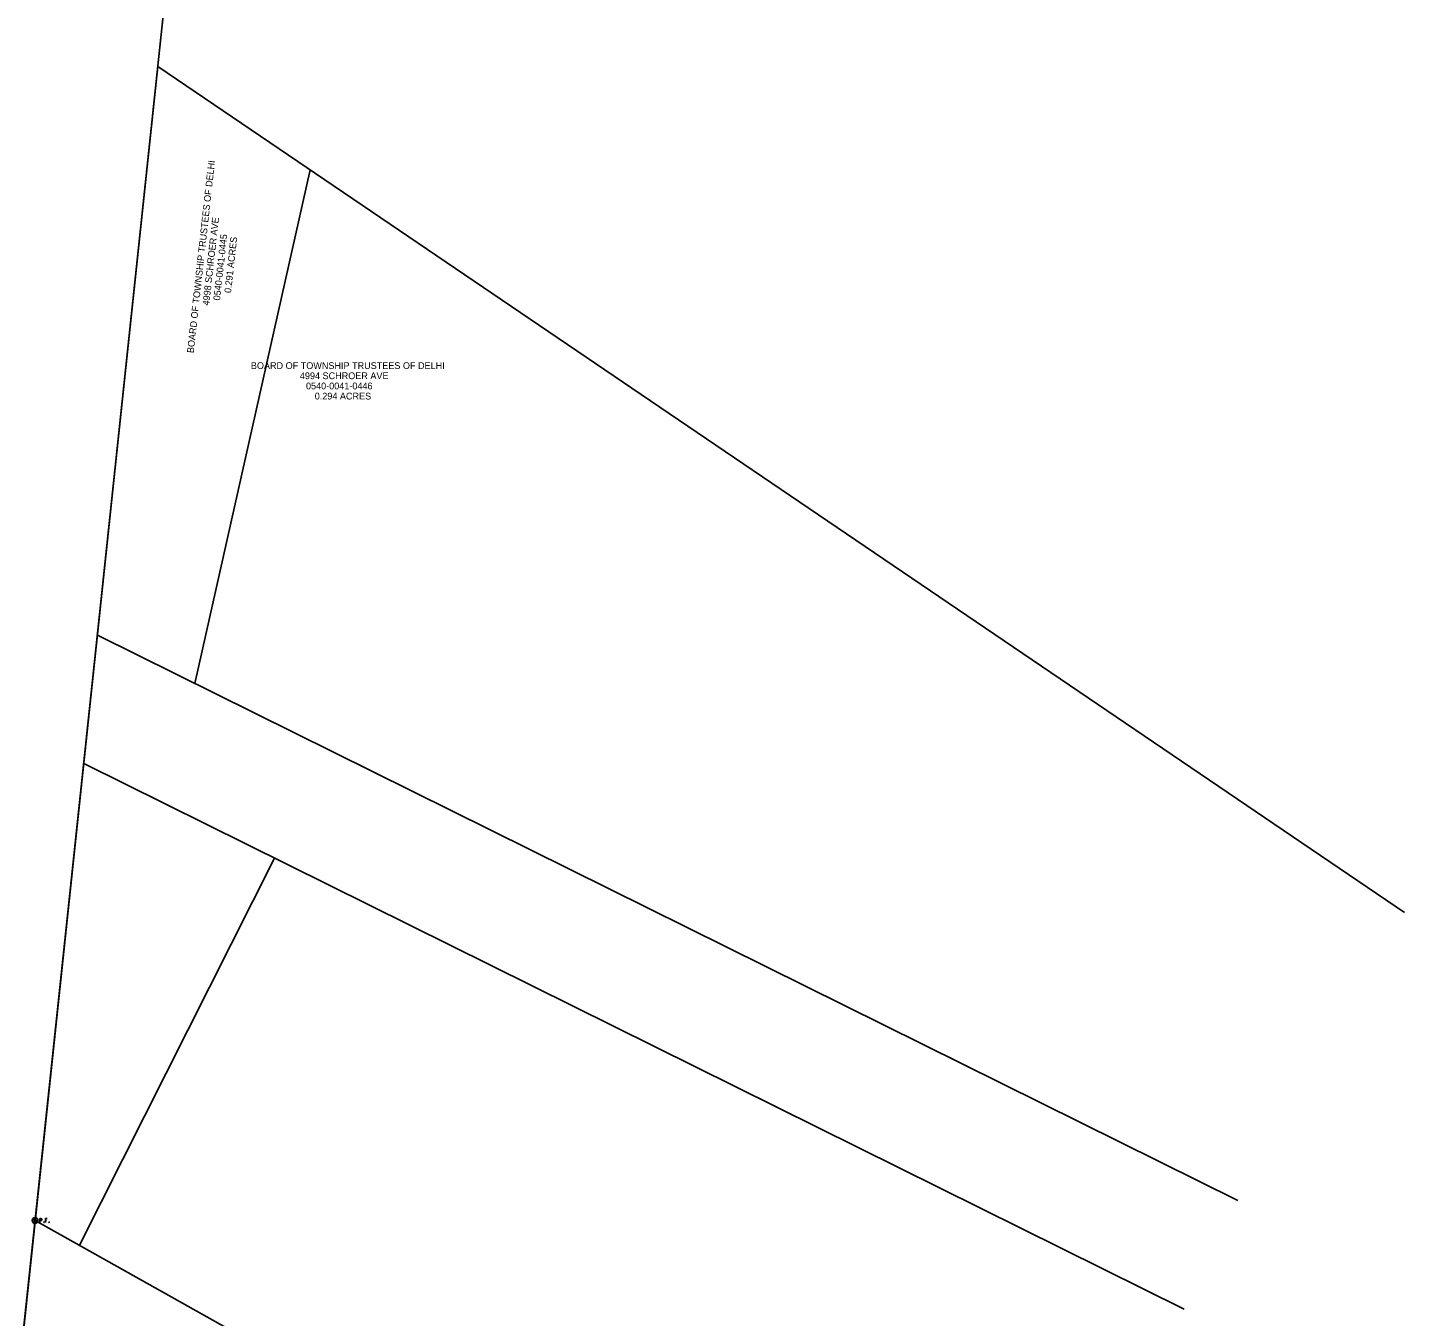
# Model space of a CAD drawing. Extents: x 1369159 to 1370720, y 404461 to 406422.
# Drawn here: x 1369899 to 1370468, y 404732 to 405265 of the extents above; entities that cross this region are included whole.
import ezdxf

# ---------------------------------------------------------------- set-up
doc = ezdxf.new("R2010")
doc.units = 0
for name, color, linetype in [('Default', 7, 'Continuous'), ('DR_P_Cells', 7, 'Continuous'), ('DR_P_Storm_Sewer', 7, 'Continuous'), ('GK_Drainage_Nodes', 7, 'Continuous'), ('SC_Scratch1', 7, 'Continuous')]:
    doc.layers.add(name, color=color, linetype=linetype)

msp = doc.modelspace()

# ---------------------------------------------------------------- linework, layer by layer
at = {"layer": 'Default'}
msp.add_line((1369966.45, 405374.29), (1369897.64, 404726.71), dxfattribs=at)
at = {"layer": 'DR_P_Cells'}
msp.add_line((1369966.45, 405374.29), (1369869.42, 404461.09), dxfattribs=at)
at = {"layer": 'DR_P_Storm_Sewer'}
for p, q in [((1369953.08, 405248.46), (1369902.42, 404771.6)), ((1370468.19, 404898.85), (1369953.08, 405248.46)), ((1369968.43, 404993.5), (1370015.99, 405205.75)), ((1369928.11, 405013.49), (1370399.37, 404779.85)), ((1369922.48, 404960.47), (1370377.17, 404735.05)), ((1369920.67, 404761.37), (1370001.31, 404921.39)), ((1369902.42, 404771.6), (1370172.14, 404620.45))]:
    msp.add_line(p, q, dxfattribs=at)
at = {"layer": 'SC_Scratch1'}
for p, q in [((1369904.36, 404770.8), (1369904.36, 404772.4)), ((1369904.36, 404772.4), (1369904.89, 404772.4)), ((1369904.89, 404771.62), (1369904.36, 404771.62)), ((1369904.89, 404772.4), (1369904.94, 404772.39)), ((1369904.98, 404771.63), (1369904.89, 404771.62)), ((1369904.94, 404772.39), (1369905.02, 404772.36)), ((1369905.03, 404771.66), (1369904.98, 404771.63)), ((1369905.02, 404772.36), (1369905.05, 404772.34)), ((1369905.07, 404771.68), (1369905.03, 404771.66)), ((1369905.05, 404772.34), (1369905.09, 404772.31)), ((1369905.11, 404771.72), (1369905.07, 404771.68)), ((1369905.09, 404772.31), (1369905.13, 404772.25)), ((1369905.15, 404771.81), (1369905.11, 404771.72)), ((1369905.13, 404772.25), (1369905.16, 404772.19)), ((1369905.18, 404771.88), (1369905.15, 404771.81)), ((1369905.16, 404772.19), (1369905.19, 404772.09)), ((1369905.19, 404771.93), (1369905.18, 404771.88)), ((1369905.19, 404772.09), (1369905.19, 404771.93)), ((1369905.94, 404770.94), (1369905.97, 404770.99)), ((1369905.94, 404770.88), (1369905.94, 404770.94)), ((1369905.97, 404770.83), (1369905.94, 404770.88)), ((1369905.97, 404770.99), (1369906, 404771.02)), ((1369906, 404770.8), (1369905.97, 404770.83)), ((1369906, 404771.02), (1369906.06, 404771.02)), ((1369906.06, 404770.8), (1369906, 404770.8)), ((1369906.06, 404771.02), (1369906.09, 404770.99)), ((1369906.09, 404770.83), (1369906.06, 404770.8)), ((1369906.09, 404770.99), (1369906.12, 404770.94)), ((1369906.12, 404770.88), (1369906.09, 404770.83)), ((1369906.12, 404770.94), (1369906.12, 404770.88)), ((1369907.37, 404772.4), (1369906.61, 404772.4)), ((1369906.61, 404772.4), (1369906.61, 404770.8)), ((1369906.61, 404771.62), (1369907.15, 404771.62)), ((1369908.09, 404770.94), (1369908.12, 404770.99)), ((1369908.09, 404770.88), (1369908.09, 404770.94)), ((1369908.12, 404770.83), (1369908.09, 404770.88)), ((1369908.12, 404770.99), (1369908.15, 404771.02)), ((1369908.15, 404770.8), (1369908.12, 404770.83)), ((1369908.15, 404771.02), (1369908.21, 404771.02)), ((1369908.21, 404770.8), (1369908.15, 404770.8)), ((1369908.21, 404771.02), (1369908.24, 404770.99)), ((1369908.24, 404770.83), (1369908.21, 404770.8)), ((1369908.24, 404770.99), (1369908.27, 404770.94)), ((1369908.27, 404770.88), (1369908.24, 404770.83)), ((1369908.27, 404770.94), (1369908.27, 404770.88))]:
    msp.add_line(p, q, dxfattribs=at)
for radius in [1.2, 0.495]:
    msp.add_circle((1369902.36, 404771.6), radius, dxfattribs=at)

# ---------------------------------------------------------------- texts
at = {"layer": 'GK_Drainage_Nodes'}
for s, p in [('BOARD OF TOWNSHIP TRUSTEES OF DELHI', (1369967.9, 405129.9)), ('4998 SCHROER AVE', (1369974.31, 405149.56)), ('0540-0041-0445', (1369978.77, 405151.65)), ('0.291 ACRES', (1369983.33, 405154.72))]:
    msp.add_text(s, height=2.8, rotation=83.6545, dxfattribs=at).set_placement(p)
for s, p in [('BOARD OF TOWNSHIP TRUSTEES OF DELHI', (1369991.54, 405123.44)), ('4994 SCHROER AVE', (1370011.79, 405119.24)), ('0540-0041-0446', (1370014.32, 405115.04)), ('0.294 ACRES', (1370017.92, 405110.84))]:
    msp.add_text(s, height=2.8, dxfattribs=at).set_placement(p)

doc.saveas('drawing.dxf')
